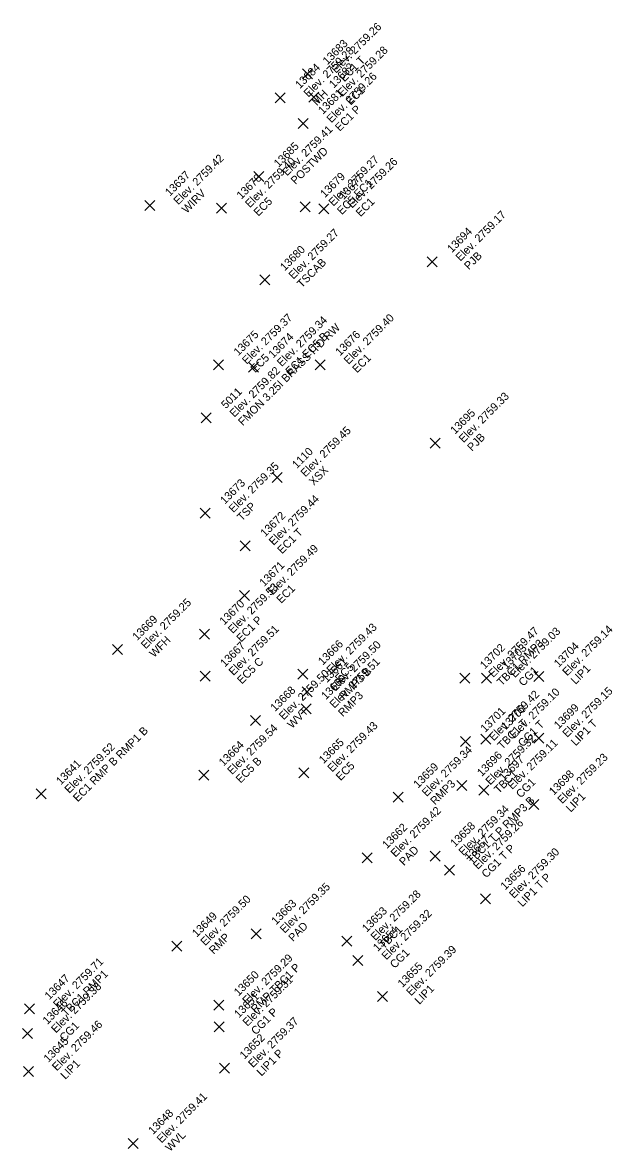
# Model space of a CAD drawing. Extents: x 2493999 to 2503109, y 700767 to 706646.
# Drawn here: x 2502239.5 to 2502257.19, y 702678.15 to 702711.97 of the extents above; entities that cross this region are included whole.
import ezdxf

# ---------------------------------------------------------------- set-up
doc = ezdxf.new("R2010")
doc.units = 0
doc.layers.add('ALG_CL_BLUE_Horiz', color=7, linetype='Continuous')
doc.layers.add('DES_SURFACE_Existing-Ground', color=7, linetype='Continuous')

msp = doc.modelspace()

# ---------------------------------------------------------------- linework, layer by layer
at = {"layer": 'ALG_CL_BLUE_Horiz'}
for points in [[(2502248.047, 702710.438), (2502247.897, 702710.588), (2502248.047, 702710.438), (2502247.897, 702710.288), (2502248.047, 702710.438), (2502248.197, 702710.288), (2502248.047, 702710.438), (2502248.197, 702710.588)], [(2502247.22, 702709.719), (2502247.07, 702709.869), (2502247.22, 702709.719), (2502247.07, 702709.569), (2502247.22, 702709.719), (2502247.37, 702709.569), (2502247.22, 702709.719), (2502247.37, 702709.869)], [(2502248.237, 702709.736), (2502248.087, 702709.886), (2502248.237, 702709.736), (2502248.087, 702709.586), (2502248.237, 702709.736), (2502248.387, 702709.586), (2502248.237, 702709.736), (2502248.387, 702709.886)], [(2502247.909, 702708.951), (2502247.759, 702709.101), (2502247.909, 702708.951), (2502247.759, 702708.801), (2502247.909, 702708.951), (2502248.059, 702708.801), (2502247.909, 702708.951), (2502248.059, 702709.101)], [(2502246.581, 702707.359), (2502246.431, 702707.509), (2502246.581, 702707.359), (2502246.431, 702707.209), (2502246.581, 702707.359), (2502246.731, 702707.209), (2502246.581, 702707.359), (2502246.731, 702707.509)], [(2502243.318, 702706.493), (2502243.168, 702706.643), (2502243.318, 702706.493), (2502243.168, 702706.343), (2502243.318, 702706.493), (2502243.468, 702706.343), (2502243.318, 702706.493), (2502243.468, 702706.643)], [(2502245.465, 702706.405), (2502245.315, 702706.555), (2502245.465, 702706.405), (2502245.315, 702706.255), (2502245.465, 702706.405), (2502245.615, 702706.255), (2502245.465, 702706.405), (2502245.615, 702706.555)], [(2502247.97, 702706.452), (2502247.82, 702706.602), (2502247.97, 702706.452), (2502247.82, 702706.302), (2502247.97, 702706.452), (2502248.12, 702706.302), (2502247.97, 702706.452), (2502248.12, 702706.602)], [(2502248.532, 702706.393), (2502248.382, 702706.543), (2502248.532, 702706.393), (2502248.382, 702706.243), (2502248.532, 702706.393), (2502248.682, 702706.243), (2502248.532, 702706.393), (2502248.682, 702706.543)], [(2502251.78, 702704.801), (2502251.63, 702704.951), (2502251.78, 702704.801), (2502251.63, 702704.651), (2502251.78, 702704.801), (2502251.93, 702704.651), (2502251.78, 702704.801), (2502251.93, 702704.951)], [(2502246.769, 702704.259), (2502246.619, 702704.409), (2502246.769, 702704.259), (2502246.619, 702704.109), (2502246.769, 702704.259), (2502246.919, 702704.109), (2502246.769, 702704.259), (2502246.919, 702704.409)], [(2502245.375, 702701.711), (2502245.225, 702701.861), (2502245.375, 702701.711), (2502245.225, 702701.561), (2502245.375, 702701.711), (2502245.525, 702701.561), (2502245.375, 702701.711), (2502245.525, 702701.861)], [(2502246.422, 702701.639), (2502246.272, 702701.789), (2502246.422, 702701.639), (2502246.272, 702701.489), (2502246.422, 702701.639), (2502246.572, 702701.489), (2502246.422, 702701.639), (2502246.572, 702701.789)], [(2502248.425, 702701.708), (2502248.275, 702701.858), (2502248.425, 702701.708), (2502248.275, 702701.558), (2502248.425, 702701.708), (2502248.575, 702701.558), (2502248.425, 702701.708), (2502248.575, 702701.858)], [(2502245.002, 702700.123), (2502244.852, 702700.273), (2502245.002, 702700.123), (2502244.852, 702699.973), (2502245.002, 702700.123), (2502245.152, 702699.973), (2502245.002, 702700.123), (2502245.152, 702700.273)], [(2502251.874, 702699.359), (2502251.724, 702699.509), (2502251.874, 702699.359), (2502251.724, 702699.209), (2502251.874, 702699.359), (2502252.024, 702699.209), (2502251.874, 702699.359), (2502252.024, 702699.509)], [(2502247.131, 702698.33), (2502246.981, 702698.48), (2502247.131, 702698.33), (2502246.981, 702698.18), (2502247.131, 702698.33), (2502247.281, 702698.18), (2502247.131, 702698.33), (2502247.281, 702698.48)], [(2502244.972, 702697.26), (2502244.822, 702697.41), (2502244.972, 702697.26), (2502244.822, 702697.11), (2502244.972, 702697.26), (2502245.122, 702697.11), (2502244.972, 702697.26), (2502245.122, 702697.41)], [(2502246.179, 702696.28), (2502246.029, 702696.43), (2502246.179, 702696.28), (2502246.029, 702696.13), (2502246.179, 702696.28), (2502246.329, 702696.13), (2502246.179, 702696.28), (2502246.329, 702696.43)], [(2502246.151, 702694.793), (2502246.001, 702694.943), (2502246.151, 702694.793), (2502246.001, 702694.643), (2502246.151, 702694.793), (2502246.301, 702694.643), (2502246.151, 702694.793), (2502246.301, 702694.943)], [(2502244.95, 702693.636), (2502244.8, 702693.786), (2502244.95, 702693.636), (2502244.8, 702693.486), (2502244.95, 702693.636), (2502245.1, 702693.486), (2502244.95, 702693.636), (2502245.1, 702693.786)], [(2502242.341, 702693.173), (2502242.191, 702693.323), (2502242.341, 702693.173), (2502242.191, 702693.023), (2502242.341, 702693.173), (2502242.491, 702693.023), (2502242.341, 702693.173), (2502242.491, 702693.323)], [(2502244.972, 702692.379), (2502244.822, 702692.529), (2502244.972, 702692.379), (2502244.822, 702692.229), (2502244.972, 702692.379), (2502245.122, 702692.229), (2502244.972, 702692.379), (2502245.122, 702692.529)], [(2502247.908, 702692.432), (2502247.758, 702692.582), (2502247.908, 702692.432), (2502247.758, 702692.282), (2502247.908, 702692.432), (2502248.058, 702692.282), (2502247.908, 702692.432), (2502248.058, 702692.582)], [(2502254.984, 702692.367), (2502254.834, 702692.517), (2502254.984, 702692.367), (2502254.834, 702692.217), (2502254.984, 702692.367), (2502255.134, 702692.217), (2502254.984, 702692.367), (2502255.134, 702692.517)], [(2502252.766, 702692.318), (2502252.616, 702692.468), (2502252.766, 702692.318), (2502252.616, 702692.168), (2502252.766, 702692.318), (2502252.916, 702692.168), (2502252.766, 702692.318), (2502252.916, 702692.468)], [(2502253.415, 702692.311), (2502253.265, 702692.461), (2502253.415, 702692.311), (2502253.265, 702692.161), (2502253.415, 702692.311), (2502253.565, 702692.161), (2502253.415, 702692.311), (2502253.565, 702692.461)], [(2502248.031, 702691.906), (2502247.881, 702692.056), (2502248.031, 702691.906), (2502247.881, 702691.756), (2502248.031, 702691.906), (2502248.181, 702691.756), (2502248.031, 702691.906), (2502248.181, 702692.056)], [(2502248.001, 702691.398), (2502247.851, 702691.548), (2502248.001, 702691.398), (2502247.851, 702691.248), (2502248.001, 702691.398), (2502248.151, 702691.248), (2502248.001, 702691.398), (2502248.151, 702691.548)], [(2502246.48, 702691.044), (2502246.33, 702691.194), (2502246.48, 702691.044), (2502246.33, 702690.894), (2502246.48, 702691.044), (2502246.63, 702690.894), (2502246.48, 702691.044), (2502246.63, 702691.194)], [(2502252.78, 702690.418), (2502252.63, 702690.568), (2502252.78, 702690.418), (2502252.63, 702690.268), (2502252.78, 702690.418), (2502252.93, 702690.268), (2502252.78, 702690.418), (2502252.93, 702690.568)], [(2502253.397, 702690.489), (2502253.247, 702690.639), (2502253.397, 702690.489), (2502253.247, 702690.339), (2502253.397, 702690.489), (2502253.547, 702690.339), (2502253.397, 702690.489), (2502253.547, 702690.639)], [(2502254.984, 702690.521), (2502254.834, 702690.671), (2502254.984, 702690.521), (2502254.834, 702690.371), (2502254.984, 702690.521), (2502255.134, 702690.371), (2502254.984, 702690.521), (2502255.134, 702690.671)], [(2502244.932, 702689.405), (2502244.782, 702689.555), (2502244.932, 702689.405), (2502244.782, 702689.255), (2502244.932, 702689.405), (2502245.082, 702689.255), (2502244.932, 702689.405), (2502245.082, 702689.555)], [(2502247.934, 702689.481), (2502247.784, 702689.631), (2502247.934, 702689.481), (2502247.784, 702689.331), (2502247.934, 702689.481), (2502248.084, 702689.331), (2502247.934, 702689.481), (2502248.084, 702689.631)], [(2502252.678, 702689.095), (2502252.528, 702689.245), (2502252.678, 702689.095), (2502252.528, 702688.945), (2502252.678, 702689.095), (2502252.828, 702688.945), (2502252.678, 702689.095), (2502252.828, 702689.245)], [(2502240.05, 702688.844), (2502239.9, 702688.994), (2502240.05, 702688.844), (2502239.9, 702688.694), (2502240.05, 702688.844), (2502240.2, 702688.694), (2502240.05, 702688.844), (2502240.2, 702688.994)], [(2502250.767, 702688.749), (2502250.617, 702688.899), (2502250.767, 702688.749), (2502250.617, 702688.599), (2502250.767, 702688.749), (2502250.917, 702688.599), (2502250.767, 702688.749), (2502250.917, 702688.899)], [(2502253.338, 702688.961), (2502253.188, 702689.111), (2502253.338, 702688.961), (2502253.188, 702688.811), (2502253.338, 702688.961), (2502253.488, 702688.811), (2502253.338, 702688.961), (2502253.488, 702689.111)], [(2502254.836, 702688.531), (2502254.686, 702688.681), (2502254.836, 702688.531), (2502254.686, 702688.381), (2502254.836, 702688.531), (2502254.986, 702688.381), (2502254.836, 702688.531), (2502254.986, 702688.681)], [(2502251.873, 702686.978), (2502251.723, 702687.128), (2502251.873, 702686.978), (2502251.723, 702686.828), (2502251.873, 702686.978), (2502252.023, 702686.828), (2502251.873, 702686.978), (2502252.023, 702687.128)], [(2502249.832, 702686.932), (2502249.682, 702687.082), (2502249.832, 702686.932), (2502249.682, 702686.782), (2502249.832, 702686.932), (2502249.982, 702686.782), (2502249.832, 702686.932), (2502249.982, 702687.082)], [(2502252.305, 702686.562), (2502252.155, 702686.712), (2502252.305, 702686.562), (2502252.155, 702686.412), (2502252.305, 702686.562), (2502252.455, 702686.412), (2502252.305, 702686.562), (2502252.455, 702686.712)], [(2502253.383, 702685.694), (2502253.233, 702685.844), (2502253.383, 702685.694), (2502253.233, 702685.544), (2502253.383, 702685.694), (2502253.533, 702685.544), (2502253.383, 702685.694), (2502253.533, 702685.844)], [(2502246.508, 702684.651), (2502246.358, 702684.801), (2502246.508, 702684.651), (2502246.358, 702684.501), (2502246.508, 702684.651), (2502246.658, 702684.501), (2502246.508, 702684.651), (2502246.658, 702684.801)], [(2502244.128, 702684.276), (2502243.978, 702684.426), (2502244.128, 702684.276), (2502243.978, 702684.126), (2502244.128, 702684.276), (2502244.278, 702684.126), (2502244.128, 702684.276), (2502244.278, 702684.426)], [(2502249.228, 702684.43), (2502249.078, 702684.58), (2502249.228, 702684.43), (2502249.078, 702684.28), (2502249.228, 702684.43), (2502249.378, 702684.28), (2502249.228, 702684.43), (2502249.378, 702684.58)], [(2502249.557, 702683.85), (2502249.407, 702684), (2502249.557, 702683.85), (2502249.407, 702683.7), (2502249.557, 702683.85), (2502249.707, 702683.7), (2502249.557, 702683.85), (2502249.707, 702684)], [(2502250.297, 702682.771), (2502250.147, 702682.921), (2502250.297, 702682.771), (2502250.147, 702682.621), (2502250.297, 702682.771), (2502250.447, 702682.621), (2502250.297, 702682.771), (2502250.447, 702682.921)], [(2502239.707, 702682.402), (2502239.557, 702682.552), (2502239.707, 702682.402), (2502239.557, 702682.252), (2502239.707, 702682.402), (2502239.857, 702682.252), (2502239.707, 702682.402), (2502239.857, 702682.552)], [(2502245.384, 702682.513), (2502245.234, 702682.663), (2502245.384, 702682.513), (2502245.234, 702682.363), (2502245.384, 702682.513), (2502245.534, 702682.363), (2502245.384, 702682.513), (2502245.534, 702682.663)], [(2502239.646, 702681.66), (2502239.496, 702681.81), (2502239.646, 702681.66), (2502239.496, 702681.51), (2502239.646, 702681.66), (2502239.796, 702681.51), (2502239.646, 702681.66), (2502239.796, 702681.81)], [(2502245.391, 702681.857), (2502245.241, 702682.007), (2502245.391, 702681.857), (2502245.241, 702681.707), (2502245.391, 702681.857), (2502245.541, 702681.707), (2502245.391, 702681.857), (2502245.541, 702682.007)], [(2502239.676, 702680.522), (2502239.526, 702680.672), (2502239.676, 702680.522), (2502239.526, 702680.372), (2502239.676, 702680.522), (2502239.826, 702680.372), (2502239.676, 702680.522), (2502239.826, 702680.672)], [(2502245.558, 702680.62), (2502245.408, 702680.77), (2502245.558, 702680.62), (2502245.408, 702680.47), (2502245.558, 702680.62), (2502245.708, 702680.47), (2502245.558, 702680.62), (2502245.708, 702680.77)], [(2502242.816, 702678.361), (2502242.666, 702678.511), (2502242.816, 702678.361), (2502242.666, 702678.211), (2502242.816, 702678.361), (2502242.966, 702678.211), (2502242.816, 702678.361), (2502242.966, 702678.511)]]:
    msp.add_lwpolyline(points, dxfattribs=at)

# ---------------------------------------------------------------- texts
at = {"layer": 'DES_SURFACE_Existing-Ground'}
for s, p in [('Elev. 2759.26', (2502248.896, 702710.438)), ('13683', (2502248.641, 702710.693)), ('Elev. 2759.28', (2502248.069, 702709.719)), ('Elev. 2759.28', (2502249.086, 702709.736)), ('EC1 T', (2502249.15, 702710.183)), ('13684', (2502247.814, 702709.974)), ('Elev. 2759.26', (2502248.758, 702708.951)), ('13682', (2502248.831, 702709.991)), ('MH', (2502248.323, 702709.464)), ('13681', (2502248.503, 702709.206)), ('EC1', (2502249.34, 702709.481)), ('EC1 P', (2502249.012, 702708.696)), ('Elev. 2759.41', (2502247.43, 702707.359)), ('13685', (2502247.175, 702707.614)), ('POSTWD', (2502247.684, 702707.104)), ('Elev. 2759.42', (2502244.167, 702706.493)), ('Elev. 2759.40', (2502246.314, 702706.405)), ('Elev. 2759.27', (2502248.819, 702706.452)), ('Elev. 2759.26', (2502249.381, 702706.393)), ('13637', (2502243.912, 702706.748)), ('13678', (2502246.059, 702706.66)), ('13679', (2502248.564, 702706.707)), ('13677', (2502249.126, 702706.648)), ('EC5 EC1', (2502249.073, 702706.197)), ('WIRV', (2502244.421, 702706.238)), ('EC5', (2502246.568, 702706.15)), ('EC1', (2502249.635, 702706.138)), ('Elev. 2759.17', (2502252.629, 702704.801)), ('Elev. 2759.27', (2502247.618, 702704.259)), ('13694', (2502252.374, 702705.056)), ('13680', (2502247.363, 702704.514)), ('PJB', (2502252.883, 702704.546)), ('TSCAB', (2502247.872, 702704.004)), ('Elev. 2759.37', (2502246.224, 702701.711)), ('Elev. 2759.34', (2502247.271, 702701.639)), ('Elev. 2759.40', (2502249.274, 702701.708)), ('13675', (2502245.969, 702701.966)), ('FMON 3.25I BRASS ITD RW', (2502246.105, 702699.868)), ('13674', (2502247.016, 702701.894)), ('EC1 EC5 B', (2502247.525, 702701.384)), ('13676', (2502249.019, 702701.963)), ('EC5', (2502246.478, 702701.456)), ('EC1', (2502249.528, 702701.453)), ('Elev. 2759.82', (2502245.851, 702700.123)), ('5011', (2502245.596, 702700.378)), ('Elev. 2759.33', (2502252.723, 702699.359)), ('13695', (2502252.468, 702699.614)), ('Elev. 2759.45', (2502247.98, 702698.33)), ('PJB', (2502252.977, 702699.104)), ('1110', (2502247.725, 702698.585)), ('Elev. 2759.35', (2502245.821, 702697.26)), ('XSX', (2502248.234, 702698.075)), ('13673', (2502245.566, 702697.515)), ('TSP', (2502246.075, 702697.005)), ('Elev. 2759.44', (2502247.028, 702696.28)), ('13672', (2502246.773, 702696.535)), ('EC1 T', (2502247.282, 702696.025)), ('Elev. 2759.49', (2502247, 702694.793)), ('13671', (2502246.745, 702695.048)), ('Elev. 2759.53', (2502245.799, 702693.636)), ('EC1', (2502247.254, 702694.538)), ('Elev. 2759.25', (2502243.19, 702693.173)), ('13670', (2502245.544, 702693.891)), ('13669', (2502242.935, 702693.428)), ('Elev. 2759.51', (2502245.821, 702692.379)), ('EC1 P', (2502246.053, 702693.381)), ('Elev. 2759.43', (2502248.757, 702692.432)), ('Elev. 2759.47', (2502253.615, 702692.318)), ('Elev. 2759.14', (2502255.833, 702692.367)), ('WFH', (2502243.444, 702692.918)), ('Elev. 2759.03', (2502254.264, 702692.311)), ('13667', (2502245.566, 702692.634)), ('13666', (2502248.502, 702692.687)), ('Elev. 2759.50', (2502248.88, 702691.906)), ('13702', (2502253.36, 702692.573)), ('TBC1 RMP3', (2502253.869, 702692.063)), ('13703', (2502254.009, 702692.566)), ('13704', (2502255.578, 702692.622)), ('EC5 C', (2502246.075, 702692.124)), ('13661', (2502248.625, 702692.161)), ('Elev. 2759.51', (2502248.85, 702691.398)), ('Elev. 2759.50', (2502247.329, 702691.044)), ('EC5', (2502249.011, 702692.177)), ('RMP3 B', (2502249.134, 702691.651)), ('CG1', (2502254.518, 702692.056)), ('LIP1', (2502256.087, 702692.112)), ('13660', (2502248.595, 702691.653)), ('13668', (2502247.074, 702691.299)), ('RMP3', (2502249.104, 702691.143)), ('Elev. 2759.42', (2502253.629, 702690.418)), ('Elev. 2759.10', (2502254.246, 702690.489)), ('Elev. 2759.15', (2502255.833, 702690.521)), ('13700', (2502253.991, 702690.744)), ('13699', (2502255.578, 702690.776)), ('WVT', (2502247.583, 702690.789)), ('13701', (2502253.374, 702690.673)), ('EC1 RMP B RMP1 B', (2502241.153, 702688.589)), ('Elev. 2759.54', (2502245.781, 702689.405)), ('Elev. 2759.43', (2502248.783, 702689.481)), ('TBC1 T', (2502253.883, 702690.163)), ('CG1 T', (2502254.5, 702690.234)), ('LIP1 T', (2502256.087, 702690.266)), ('13665', (2502248.528, 702689.736)), ('Elev. 2759.32', (2502253.527, 702689.095)), ('Elev. 2759.11', (2502254.187, 702688.961)), ('Elev. 2759.52', (2502240.899, 702688.844)), ('13664', (2502245.526, 702689.66)), ('Elev. 2759.34', (2502251.616, 702688.749)), ('13641', (2502240.644, 702689.099)), ('EC5 B', (2502246.035, 702689.15)), ('EC5', (2502249.037, 702689.226)), ('13696', (2502253.272, 702689.35)), ('13697', (2502253.932, 702689.216)), ('Elev. 2759.23', (2502255.685, 702688.531)), ('13659', (2502251.361, 702689.004)), ('TBC1', (2502253.781, 702688.84)), ('13698', (2502255.43, 702688.786)), ('RMP3', (2502251.87, 702688.494)), ('CG1', (2502254.441, 702688.706)), ('LIP1', (2502255.939, 702688.276)), ('Elev. 2759.42', (2502250.681, 702686.932)), ('Elev. 2759.34', (2502252.722, 702686.978)), ('TBC1 T P RMP3 B', (2502252.976, 702686.723)), ('13662', (2502250.426, 702687.187)), ('13658', (2502252.467, 702687.233)), ('Elev. 2759.26', (2502253.154, 702686.562)), ('13657', (2502252.899, 702686.817)), ('PAD', (2502250.935, 702686.677)), ('CG1 T P', (2502253.408, 702686.307)), ('Elev. 2759.30', (2502254.232, 702685.694)), ('13656', (2502253.977, 702685.949)), ('LIP1 T P', (2502254.486, 702685.439)), ('Elev. 2759.35', (2502247.357, 702684.651)), ('Elev. 2759.50', (2502244.977, 702684.276)), ('Elev. 2759.28', (2502250.077, 702684.43)), ('13663', (2502247.102, 702684.906)), ('13653', (2502249.822, 702684.685)), ('13649', (2502244.722, 702684.531)), ('Elev. 2759.32', (2502250.406, 702683.85)), ('PAD', (2502247.611, 702684.396)), ('13654', (2502250.151, 702684.105)), ('TBC1', (2502250.331, 702684.175)), ('RMP', (2502245.231, 702684.021)), ('CG1', (2502250.66, 702683.595)), ('Elev. 2759.39', (2502251.146, 702682.771)), ('Elev. 2759.71', (2502240.556, 702682.402)), ('Elev. 2759.29', (2502246.233, 702682.513)), ('RMP TBC1 P', (2502246.487, 702682.258)), ('13655', (2502250.891, 702683.026)), ('13647', (2502240.301, 702682.657)), ('TBC1 RMP1', (2502240.81, 702682.147)), ('13650', (2502245.978, 702682.768)), ('Elev. 2759.38', (2502240.495, 702681.66)), ('Elev. 2759.31', (2502246.24, 702681.857)), ('LIP1', (2502251.4, 702682.516)), ('13646', (2502240.24, 702681.915)), ('13651', (2502245.985, 702682.112)), ('CG1 P', (2502246.494, 702681.602)), ('Elev. 2759.46', (2502240.525, 702680.522)), ('Elev. 2759.37', (2502246.407, 702680.62)), ('CG1', (2502240.749, 702681.405)), ('13645', (2502240.27, 702680.777)), ('13652', (2502246.152, 702680.875)), ('LIP1 P', (2502246.661, 702680.365)), ('LIP1', (2502240.779, 702680.267)), ('Elev. 2759.41', (2502243.665, 702678.361)), ('13648', (2502243.41, 702678.616)), ('WVL', (2502243.919, 702678.106))]:
    msp.add_text(s, height=0.24, rotation=45, dxfattribs=at).set_placement(p)

doc.saveas('drawing.dxf')
